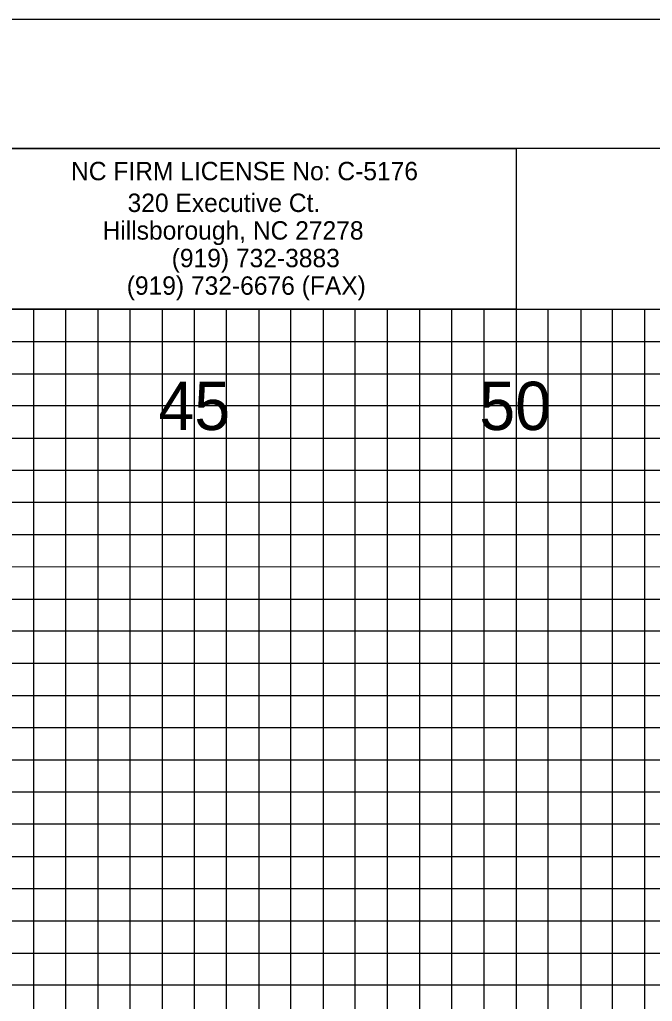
# Model space of a CAD drawing. Extents: x -7 to 162, y -2 to 327.
# Drawn here: x 122.28 to 132.12, y 201.75 to 217 of the extents above; entities that cross this region are included whole.
import ezdxf

# ---------------------------------------------------------------- set-up
doc = ezdxf.new("R2010")
doc.units = 0
for name, color, linetype in [('Exist Cross Section Cell', 7, 'Continuous'), ('Prop CMT Guardrail Widen Shoulder', 7, 'Continuous'), ('Prop CMT Pvmt Course 3', 7, 'Continuous'), ('Prop CMT Shld Paved Course 1', 7, 'Continuous'), ('Prop CMT Shld Paved Course 2', 7, 'Continuous'), ('Prop CMT Shld Paved Course 3', 7, 'Continuous'), ('Prop CMT Slope Grass', 7, 'Continuous'), ('Prop CMT Subgrade Earthwork', 7, 'Continuous'), ('Scratch_Level_0', 7, 'Continuous'), ('Scratch_Level_3', 7, 'Continuous')]:
    doc.layers.add(name, color=color, linetype=linetype)

msp = doc.modelspace()

# ---------------------------------------------------------------- linework, layer by layer
at = {"layer": 'Prop CMT Guardrail Widen Shoulder'}
msp.add_lwpolyline([(110.951, 215), (130, 215), (130, 212.5), (110.951, 212.5)], close=True, dxfattribs=at)
at = {"layer": 'Prop CMT Pvmt Course 3'}
msp.add_lwpolyline([(-6.7, 107.5), (161.65, 107.5), (161.65, 217), (-6.7, 217)], close=True, dxfattribs=at)
at = {"layer": 'Prop CMT Shld Paved Course 1'}
for p, q in [((130, 214.5), (130, 213.99)), ((130, 213.5), (130, 212.945)), ((0, 212), (160, 212))]:
    msp.add_line(p, q, dxfattribs=at)
for points in [[(0, 211.5), (135, 211.5), (160, 211.5)], [(160, 211), (0, 211)], [(0, 210.5), (160, 210.5)], [(160, 209.5), (0, 209.5)], [(0, 209), (160, 209)], [(160, 208.5), (0, 208.49)], [(0, 208), (160, 208)], [(160, 207), (0, 207)], [(0, 206.5), (160, 206.5), (160, 206), (0, 206)], [(0, 205.5), (160, 205.5), (160, 204.5), (0, 204.5)], [(0, 204), (160, 204), (160, 203.5), (0, 203.5)], [(0, 203), (160, 203), (160, 202), (0, 202)]]:
    msp.add_lwpolyline(points, dxfattribs=at)
at = {"layer": 'Prop CMT Shld Paved Course 2'}
for points in [[(160, 215), (0, 215), (0, 110), (160, 110)], [(140, 215), (130, 215), (130, 212.5), (140, 212.5)]]:
    msp.add_lwpolyline(points, close=True, dxfattribs=at)
at = {"layer": 'Prop CMT Shld Paved Course 3'}
for points in [[(123, 215), (123.5, 215)], [(124, 215), (124.5, 215)], [(125.5, 215), (126, 215)], [(126.5, 215), (127, 215)], [(128, 215), (128.5, 215)], [(129, 215), (129.5, 215)], [(122.5, 110), (123, 110), (123, 212.5)], [(123.5, 212.5), (123.5, 110)], [(123.5, 110), (124, 110), (124, 212.5)], [(124.5, 212.5), (124.5, 110)], [(125, 110), (125.5, 110), (125.5, 212.5)], [(126, 212.5), (126, 110)], [(126, 110), (126.5, 110), (126.5, 212.5)], [(127, 212.5), (127, 110)], [(127.5, 110), (128, 110), (128, 212.5)], [(128.5, 212.5), (128.5, 110)], [(128.5, 110), (129, 110), (129, 212.5)], [(129.5, 212.5), (129.5, 110)], [(130, 110), (130.5, 110), (130.5, 212.5), (131.01, 212.5), (131.01, 110)], [(131, 110), (131.5, 110), (131.5, 212.5), (131.995, 212.5), (131.995, 110)]]:
    msp.add_lwpolyline(points, dxfattribs=at)
at = {"layer": 'Prop CMT Slope Grass'}
for points in [[(117.5, 215), (122.5, 215)], [(127.5, 215), (129.965, 215), (130, 215), (130, 212.5), (132.495, 212.5), (132.495, 110), (137.5, 110), (137.5, 212.5), (140, 212.5)], [(0, 212.5), (137.5, 212.5)], [(0, 202.5), (160, 202.5), (160, 212.5)], [(122.5, 212.5), (122.5, 110), (127.5, 110), (127.5, 212.5)], [(160, 207.5), (0, 207.5)]]:
    msp.add_lwpolyline(points, dxfattribs=at)
at = {"layer": 'Prop CMT Subgrade Earthwork'}
msp.add_lwpolyline([(-5.4, 109.5), (161.2, 109.5), (161.2, 215), (-5.4, 215)], close=True, dxfattribs=at)
at = {"layer": 'Scratch_Level_3'}
for p, q in [((125, 215), (120, 215)), ((130, 215), (130, 110)), ((125, 110), (125, 212.5))]:
    msp.add_line(p, q, dxfattribs=at)
for points in [[(160, 212.5), (160, 205), (0, 205)], [(0, 210), (160, 210)]]:
    msp.add_lwpolyline(points, dxfattribs=at)

# ---------------------------------------------------------------- texts
at = {"layer": 'Exist Cross Section Cell'}
for s, p in [('45', (124.441, 210.625)), ('50', (129.429, 210.625))]:
    msp.add_text(s, height=0.75, dxfattribs=at).set_placement(p)
at = {"layer": 'Scratch_Level_0'}
msp.add_text('NC FIRM LICENSE No: C-5176', height=0.28573, dxfattribs=at).set_placement((123.083, 214.505))
for s, p in [('320 Executive Ct.', (123.962, 214.012)), ('Hillsborough, NC 27278', (123.573, 213.583)), ('(919) 732-3883', (124.648, 213.154)), ('(919) 732-6676 (FAX)', (123.949, 212.726))]:
    msp.add_text(s, height=0.28573, rotation=360, dxfattribs=at).set_placement(p)

doc.saveas('drawing.dxf')
